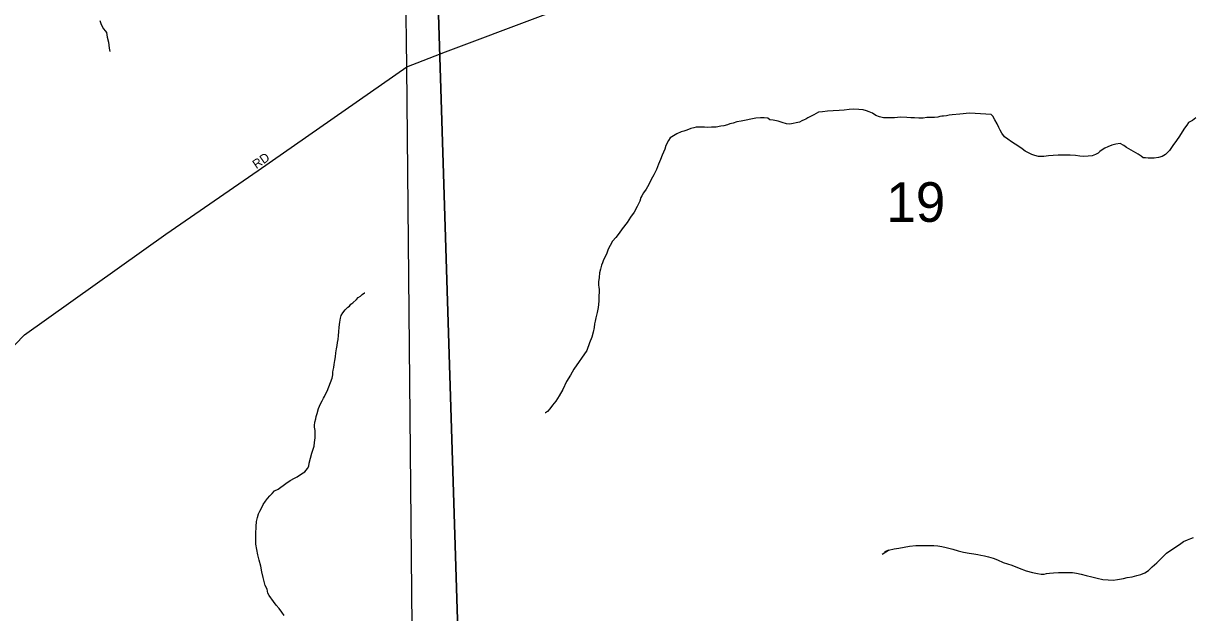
# Model space of a CAD drawing. Extents: x 2010165 to 2382125, y 1060529 to 1407316.
# Drawn here: x 2179406 to 2185920, y 1211343 to 1214628 of the extents above; entities that cross this region are included whole.
import ezdxf

# ---------------------------------------------------------------- set-up
doc = ezdxf.new("R2010")
doc.units = 0
for name, color, linetype in [('GM_X_City_Street', 7, 'Continuous'), ('GM_X_City_Street_Text', 7, 'Continuous'), ('GM_X_Major_River', 7, 'Continuous'), ('GM_X_Minor_River', 7, 'Continuous'), ('GM_X_Section', 7, 'Continuous'), ('GM_X_Section_Text', 7, 'Continuous'), ('GM_X_State_Route', 7, 'Continuous')]:
    doc.layers.add(name, color=color, linetype=linetype)

msp = doc.modelspace()

# ---------------------------------------------------------------- linework, layer by layer
at = {"layer": 'GM_X_City_Street'}
msp.add_lwpolyline([(2178423, 1211913.8), (2179036.1, 1212505.8), (2179410.9, 1212892), (2180199.4, 1213453.7), (2180714.7, 1213808.7), (2181543, 1214385.7), (2181756.8, 1214469.5), (2182287.3, 1214668.4), (2183161.5, 1214990.5), (2183684.1, 1215177.3), (2184009.7, 1215310), (2184380.9, 1215465.7), (2184751.3, 1215661.5), (2186628.9, 1216659.1), (2186954.8, 1216831.2), (2187007.7, 1216859)], dxfattribs=at)
at = {"layer": 'GM_X_Major_River'}
for points in [[(2181089.3, 1212560.6), (2181098.9, 1212576.9), (2181127, 1212649.9), (2181130.5, 1212668.1), (2181130.1, 1212684.2), (2181131.8, 1212694.2), (2181135.4, 1212710.4), (2181136.9, 1212726.5), (2181140.4, 1212748.7), (2181143.8, 1212768.8), (2181147.2, 1212791), (2181150.6, 1212813.2), (2181154.2, 1212831.4), (2181155.7, 1212849.5), (2181159.3, 1212865.6), (2181160.7, 1212887.7), (2181164.1, 1212907.9), (2181165.4, 1212934), (2181168.7, 1212962.2), (2181172.1, 1212984.4), (2181175.7, 1212998.6), (2181185.3, 1213014.9), (2181198.9, 1213031.3), (2181212.6, 1213045.7), (2181222.4, 1213052), (2181230.2, 1213062.2), (2181242, 1213070.6), (2181261.5, 1213089.2), (2181271.3, 1213099.5), (2181283.1, 1213107.8), (2181292.9, 1213116.1), (2181306.6, 1213126.5), (2181308.6, 1213126.5)], [(2180857.9, 1211327.8), (2180845.4, 1211345.6), (2180830.8, 1211365.3), (2180814.2, 1211384.9), (2180799.7, 1211404.6), (2180774.7, 1211438.1), (2180768.3, 1211452), (2180763.7, 1211473.9), (2180753.1, 1211493.7), (2180746.5, 1211515.6), (2180741.9, 1211539.6), (2180735.1, 1211569.5), (2180728.2, 1211601.5), (2180719.2, 1211635.4), (2180712.4, 1211665.3), (2180705.6, 1211695.2), (2180700.8, 1211725.2), (2180700.1, 1211751.3), (2180701.2, 1211781.5), (2180702.1, 1211823.6), (2180705.4, 1211851.8), (2180710.8, 1211874.1), (2180716.2, 1211894.3), (2180723.9, 1211908.5), (2180731.5, 1211924.8), (2180740.9, 1211945.1), (2180754.5, 1211963.6), (2180766.1, 1211979.9), (2180779.7, 1211994.3), (2180791.4, 1212006.7), (2180805.1, 1212021.1), (2180824.8, 1212031.7), (2180868.1, 1212062.9), (2180891.7, 1212079.6), (2180915.4, 1212092.3), (2180931.3, 1212100.7), (2180949, 1212113.2), (2180964.8, 1212121.7), (2180974.6, 1212128), (2180988.2, 1212146.4), (2180995.9, 1212158.6), (2180997.4, 1212176.7), (2181004.6, 1212205), (2181012, 1212231.3), (2181019.4, 1212253.6), (2181024.9, 1212271.8), (2181028.4, 1212292), (2181031.7, 1212318.2), (2181031.1, 1212338.2), (2181030.6, 1212358.3), (2181028.1, 1212376.3), (2181027.8, 1212386.3), (2181029.3, 1212404.4), (2181034.9, 1212422.7), (2181036.5, 1212436.8), (2181042.1, 1212453), (2181049.3, 1212481.3), (2181060.6, 1212507.7), (2181070.2, 1212524), (2181077.9, 1212538.2), (2181083.6, 1212548.4), (2181089.3, 1212560.6)]]:
    msp.add_lwpolyline(points, dxfattribs=at)
at = {"layer": 'GM_X_Minor_River'}
for points in [[(2179831.9, 1214643.7), (2179838.5, 1214621.8), (2179851.2, 1214598), (2179861.5, 1214586.2), (2179867.8, 1214576.4), (2179872.5, 1214550.4), (2179879.3, 1214522.5), (2179884.1, 1214490.5), (2179886.7, 1214470.5)], [(2185633.6, 1213886.9), (2185617.2, 1213898.5), (2185552, 1213936.9), (2185537.7, 1213946.6), (2185517.3, 1213958.1), (2185493.4, 1213955.5), (2185469.5, 1213948.8), (2185447.6, 1213940.2), (2185431.8, 1213931.8), (2185421.9, 1213927.5), (2185404.3, 1213913), (2185394.5, 1213904.7), (2185378.6, 1213896.2), (2185360.8, 1213889.8), (2185338.8, 1213887.2), (2185314.7, 1213886.5), (2185292.6, 1213888), (2185268.5, 1213891.3), (2185238.4, 1213892.6), (2185204.3, 1213893.7), (2185172.2, 1213892.8), (2185144.1, 1213892.1), (2185118.1, 1213889.4), (2185092.1, 1213886.7), (2185062.1, 1213885.9), (2185041.9, 1213891.4), (2185023.7, 1213896.9), (2185005.4, 1213906.5), (2184987.1, 1213916.1), (2184970.7, 1213927.7), (2184952.3, 1213941.2), (2184931.9, 1213954.8), (2184911.5, 1213968.3), (2184891.1, 1213981.8), (2184872.6, 1213995.3), (2184858.1, 1214015.1), (2184847.6, 1214032.8), (2184841.2, 1214046.7), (2184830.6, 1214068.5), (2184817.9, 1214090.3), (2184807.4, 1214110.1), (2184797.1, 1214119.8), (2184708.7, 1214125.6), (2184676.6, 1214126.7), (2184622.6, 1214121.3), (2184580.6, 1214118.2), (2184564.6, 1214115.7), (2184548.6, 1214113.3), (2184532.6, 1214110.9), (2184522.6, 1214110.6), (2184512.7, 1214108.3), (2184500.7, 1214106), (2184482.7, 1214103.5), (2184460.7, 1214103), (2184438.6, 1214102.4), (2184418.6, 1214099.8), (2184394.6, 1214099.2), (2184370.5, 1214100.6), (2184350.4, 1214102.1), (2184328.3, 1214103.5), (2184292.2, 1214104.6), (2184260.2, 1214101.7), (2184226.1, 1214100.8), (2184198, 1214102.1), (2184175.8, 1214107.5), (2184155.5, 1214115), (2184137.2, 1214126.6), (2184118.9, 1214134.1), (2184102.7, 1214139.7), (2184084.5, 1214145.3), (2184060.4, 1214148.6), (2184032.3, 1214149.9), (2184006.3, 1214147.2), (2183978.3, 1214144.5), (2183950.3, 1214141.7), (2183918.2, 1214140.9), (2183886.2, 1214138), (2183858.2, 1214135.3), (2183836.2, 1214132.7), (2183810.5, 1214118), (2183794.7, 1214111.5), (2183776.9, 1214101), (2183765.1, 1214094.7), (2183755.1, 1214090.4), (2183743.3, 1214084.1), (2183729.4, 1214077.7), (2183675.6, 1214066.2), (2183657.5, 1214067.8), (2183633.2, 1214075.1), (2183611, 1214082.6), (2183582.8, 1214087.9), (2183564.7, 1214089.4), (2183554.4, 1214099.2), (2183532.3, 1214100.6), (2183512.2, 1214102.1), (2183486.2, 1214099.4), (2183458.2, 1214094.6), (2183432.4, 1214087.9), (2183404.4, 1214083.2), (2183380.5, 1214078.5), (2183360.6, 1214072)], [(2185938.6, 1214101.7), (2185918.9, 1214087.2), (2185897.2, 1214074.5), (2185887.6, 1214060.2), (2185876, 1214043.9), (2185862.5, 1214023.4), (2185847.1, 1213998.9), (2185829.7, 1213974.4), (2185810.4, 1213947.8), (2185791.1, 1213919.1), (2185769.7, 1213896.5), (2185749.9, 1213885.9), (2185730, 1213879.4), (2185706, 1213876.8), (2185688, 1213876.3), (2185672, 1213875.9), (2185657.9, 1213877.5), (2185645.8, 1213879.2), (2185633.6, 1213886.9)], [(2183360.6, 1214072), (2183342.7, 1214067.5), (2183328.7, 1214063.1), (2183308.9, 1214056.6), (2183290.9, 1214054.1), (2183265, 1214049.4), (2183238.9, 1214048.7), (2183216.9, 1214048.1), (2183200.8, 1214049.7), (2183188.7, 1214049.4), (2183168.7, 1214048.9), (2183154.7, 1214048.5), (2183140.7, 1214046.1), (2183124.8, 1214041.7), (2183103, 1214033.1), (2183085.1, 1214026.6), (2183071.1, 1214024.2), (2183047.4, 1214011.6), (2183027.6, 1214001), (2183009.9, 1213990.5), (2183000.3, 1213974.2), (2182984.9, 1213947.7), (2182979.5, 1213927.4), (2182972, 1213909.2), (2182964.4, 1213892.9), (2182955, 1213868.6), (2182943.7, 1213842.2), (2182932.4, 1213813.8), (2182919.2, 1213783.3), (2182903.9, 1213756.8), (2182890.5, 1213730.3), (2182875.2, 1213703.8), (2182861.7, 1213683.4), (2182852.2, 1213667.1), (2182846.4, 1213656.9), (2182840.9, 1213636.7), (2182825.7, 1213606.2), (2182808.5, 1213575.6), (2182789.2, 1213547), (2182769.9, 1213518.4), (2182742.8, 1213483.5), (2182725.4, 1213459), (2182706, 1213434.4), (2182688.5, 1213413.8), (2182675.2, 1213389.4), (2182663.7, 1213369), (2182656.3, 1213346.7), (2182646.8, 1213326.4), (2182637.2, 1213310.1), (2182631.6, 1213293.9), (2182626, 1213279.7), (2182620.6, 1213257.4), (2182615.1, 1213237.2), (2182613.8, 1213211.1), (2182610.4, 1213186.9), (2182610.9, 1213168.8), (2182611.3, 1213156.8), (2182613.6, 1213144.8), (2182614, 1213128.8), (2182612.6, 1213108.7), (2182611.4, 1213078.5), (2182608.3, 1213044.3), (2182603, 1213016.1), (2182595.8, 1212985.8), (2182592.3, 1212967.6), (2182588.7, 1212953.4), (2182585.2, 1212933.3), (2182579.9, 1212907), (2182572.6, 1212878.7), (2182559.5, 1212846.3), (2182544.6, 1212803.7), (2182473.2, 1212699.4), (2182454, 1212666.8), (2182430.9, 1212632.1), (2182412.1, 1212587.4), (2182391, 1212550.7), (2182371.7, 1212522.1), (2182354.3, 1212499.6), (2182338.8, 1212479.1), (2182325.1, 1212464.6), (2182315.3, 1212456.4), (2182313.3, 1212456.3)], [(2184191.5, 1211668.6), (2184225, 1211691.5), (2184205.2, 1211681), (2184225, 1211691.5), (2184256.9, 1211698.4), (2184282.8, 1211703.1), (2184312.8, 1211707.9), (2184342.7, 1211712.7), (2184378.7, 1211717.7), (2184479, 1211716.3), (2184501.1, 1211714.9), (2184523.2, 1211711.4), (2184547.4, 1211706.1), (2184583.8, 1211697), (2184614.1, 1211687.7), (2184644.4, 1211680.5), (2184674.6, 1211675.3), (2184700.8, 1211669.9), (2184722.9, 1211666.5), (2184741.1, 1211663), (2184761.2, 1211659.5), (2184783.4, 1211654), (2184809.7, 1211646.7), (2184834, 1211637.3), (2184864.5, 1211622.1), (2184913, 1211607.3), (2184953.6, 1211590.3), (2184992.1, 1211575.2), (2185028.5, 1211566.1), (2185056.7, 1211560.8), (2185076.8, 1211557.4), (2185092.8, 1211557.8), (2185106.8, 1211560.2), (2185122.8, 1211562.6), (2185144.8, 1211565.2), (2185172.8, 1211565.9), (2185204.9, 1211566.8), (2185229, 1211567.4), (2185251, 1211566), (2185273.2, 1211562.5), (2185299.4, 1211557.2), (2185327.7, 1211549.9), (2185358, 1211542.7), (2185388.2, 1211535.5), (2185420.5, 1211528.3), (2185450.7, 1211525.1), (2185476.8, 1211523.7), (2185502.7, 1211528.4), (2185534.7, 1211533.3), (2185556.6, 1211537.9), (2185584.5, 1211542.6), (2185610.4, 1211549.3), (2185632.3, 1211555.9), (2185654.1, 1211564.5), (2185673.9, 1211577.1), (2185695.4, 1211597.7), (2185720.8, 1211620.5), (2185746.2, 1211647.3), (2185775.5, 1211674.1), (2185854.3, 1211728.4), (2185870, 1211738.9), (2185891.8, 1211749.5), (2185909.7, 1211756), (2185925.5, 1211762.4)]]:
    msp.add_lwpolyline(points, dxfattribs=at)
at = {"layer": 'GM_X_Section'}
for points in [[(2181662, 1216455.1), (2181835.9, 1210948.1), (2176227.8, 1210985.9), (2176133.3, 1216538.6)], [(2186961.3, 1216421.1), (2187059.5, 1210937.2), (2181835.9, 1210948.1), (2181662, 1216455.1)]]:
    msp.add_lwpolyline(points, close=True, dxfattribs=at)
at = {"layer": 'GM_X_State_Route'}
msp.add_lwpolyline([(2181576.3, 1210875.4), (2181543, 1214385.7), (2181536.6, 1214814.7)], dxfattribs=at)

# ---------------------------------------------------------------- texts
at = {"layer": 'GM_X_City_Street_Text'}
msp.add_text('RD', height=50, rotation=34.50794, dxfattribs=at).set_placement((2180703.7, 1213814.9))
at = {"layer": 'GM_X_Section_Text'}
msp.add_text('19', height=221, rotation=0.00001, dxfattribs=at).set_placement((2184213.6, 1213521.5))

doc.saveas('drawing.dxf')
